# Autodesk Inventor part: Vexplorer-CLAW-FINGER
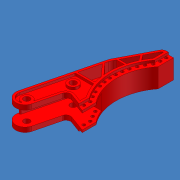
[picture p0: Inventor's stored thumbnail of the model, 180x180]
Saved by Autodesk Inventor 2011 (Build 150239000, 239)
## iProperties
Created: 2007-10
Part Number: Vexplorer-CLAW-FINGER
Document SubType Name: Modeling
Material: ABS Plastic
Density: 1.06 g/cm^3
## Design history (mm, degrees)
feature "Base1"
body "Solid1"
